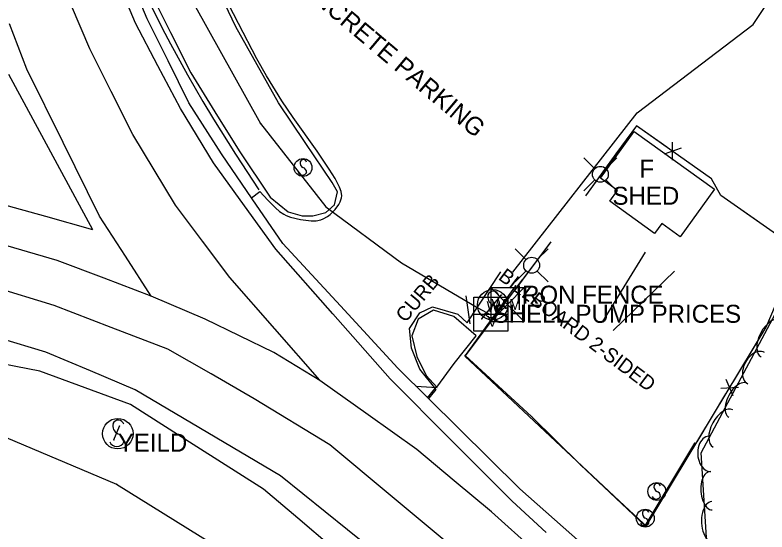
# Model space of a CAD drawing. Extents: x 1441650 to 1491889, y 345904 to 358319.
# Drawn here: x 1442426.6 to 1442635.7, y 357190.8 to 357334.5 of the extents above; entities that cross this region are included whole.
import ezdxf

# ---------------------------------------------------------------- set-up
doc = ezdxf.new("R2010")
doc.units = 0
for name, color, linetype in [('S_BUILDING', 7, 'Continuous'), ('S_BUILDING_ANNOT', 7, 'Continuous'), ('S_CURB', 7, 'Continuous'), ('S_CURB_ANNOT', 7, 'Continuous'), ('S_EDGE_CONCRETE', 7, 'Continuous'), ('S_EDGE_PAVEMENT', 7, 'Continuous'), ('S_FENCE', 7, 'Continuous'), ('S_FENCE_ANNOT', 7, 'Continuous'), ('S_MSC_PT_SYM', 7, 'Continuous'), ('S_PARKING', 7, 'Continuous'), ('S_PARKING_ANNOT', 7, 'Continuous'), ('S_PAVEMENT_CROWN', 7, 'Continuous'), ('S_SHOULDER', 7, 'Continuous'), ('S_SIGN', 7, 'Continuous'), ('S_SIGN_ANNOT', 7, 'Continuous'), ('S_TREE', 7, 'Continuous'), ('S_UTILITY_POLE', 7, 'Continuous'), ('S_UTL_PT_SYM', 7, 'Continuous'), ('S_WATER_UTILITIES', 7, 'Continuous')]:
    doc.layers.add(name, color=color, linetype=linetype)

msp = doc.modelspace()

# ---------------------------------------------------------------- linework, layer by layer
at = {"layer": 'S_BUILDING'}
msp.add_lwpolyline([(1442598.85, 357302.17), (1442621.13, 357286.07), (1442611.57, 357272.84), (1442606.46, 357276.53), (1442604.47, 357273.79), (1442592.06, 357282.76), (1442594.21, 357285.73), (1442589.45, 357289.17)], close=True, dxfattribs=at)
at = {"layer": 'S_CURB'}
msp.add_lwpolyline([(1442464.25, 357340.83), (1442469.85, 357329.65), (1442475.45, 357318.47), (1442482.16, 357307.59), (1442488.88, 357296.71), (1442497.57, 357283.85), (1442502.55, 357279.77), (1442506.49, 357278.64), (1442509.44, 357278.67), (1442513.02, 357279.61), (1442515.42, 357281.72), (1442516.3, 357285.33), (1442514.78, 357287.98), (1442507.32, 357299.06), (1442499.86, 357310.13), (1442487.99, 357331.18), (1442478.69, 357350.71)], dxfattribs=at)
msp.add_lwpolyline([(1442554.87, 357245.36), (1442548.6, 357250.71), (1442542.98, 357252.42), (1442538.71, 357249.97), (1442536.97, 357245.34), (1442538.32, 357239.58), (1442540.96, 357234.33), (1442543.88, 357231.01), (1442548.78, 357237.63)], close=True, dxfattribs=at)
at = {"layer": 'S_CURB_ANNOT'}
for p, q in [((1442553.16, 357248.64), (1442552.04, 357256.4)), ((1442544.01, 357230.87), (1442538.09, 357231.25))]:
    msp.add_line(p, q, dxfattribs=at)
at = {"layer": 'S_EDGE_CONCRETE'}
for points in [[(1442492.39, 357283.72), (1442494.68, 357285.41), (1442496.92, 357283.03), (1442499.07, 357280.86), (1442500.19, 357279.92), (1442501.37, 357279.14), (1442501.99, 357278.81), (1442503.25, 357278.31), (1442506.01, 357277.67), (1442508.91, 357277.31), (1442510.33, 357277.33), (1442511.68, 357277.58), (1442512.32, 357277.8), (1442513.53, 357278.47), (1442514.28, 357279.06), (1442515.64, 357280.48), (1442516.66, 357281.84), (1442517.05, 357282.56), (1442517.41, 357283.67), (1442517.46, 357284.25), (1442517.3, 357285.44), (1442516.88, 357286.64), (1442515.59, 357289.02), (1442513.94, 357291.68), (1442510.6, 357296.68), (1442503.98, 357306.01), (1442500.8, 357310.69), (1442496.57, 357317.59), (1442493.87, 357322.37), (1442488.7, 357332.13), (1442484.43, 357340.5)], [(1442541.81, 357227.99), (1442543.72, 357230.38), (1442539.14, 357236.06), (1442536.88, 357241.86), (1442536.34, 357247.38), (1442539.18, 357251.71), (1442542.69, 357253.36), (1442549.75, 357251.31), (1442552.37, 357248.97), (1442561.72, 357263.08)]]:
    msp.add_lwpolyline(points, dxfattribs=at)
at = {"layer": 'S_EDGE_PAVEMENT'}
for points in [[(1442574.34, 357190.65), (1442564.91, 357199.31), (1442547.91, 357216.35), (1442530.91, 357233.4), (1442515.01, 357251.41), (1442499.11, 357269.42), (1442490.43, 357281.42), (1442481.75, 357293.41), (1442472.58, 357308.49), (1442466.31, 357320.36), (1442460.05, 357332.22), (1442454.85, 357344.64), (1442449.65, 357357.05), (1442445.57, 357369.87), (1442441.49, 357382.69), (1442438.33, 357395.97), (1442435.18, 357409.25), (1442432.26, 357424.91), (1442430.21, 357443.25)], [(1442441.56, 357408.09), (1442443.15, 357400.69), (1442444.3, 357395.77), (1442446.77, 357386), (1442449.67, 357375.7), (1442451.24, 357370.58), (1442453.77, 357362.97), (1442455.66, 357357.78), (1442456.98, 357354.35), (1442459.77, 357347.53), (1442464.3, 357337.45), (1442467.54, 357330.83), (1442469.8, 357326.46), (1442474.51, 357317.84), (1442478.84, 357310.42), (1442481.81, 357305.52), (1442487.92, 357295.83), (1442494.36, 357285.94)], [(1442464.47, 357256.33), (1442457.26, 357267.43), (1442450.05, 357278.54), (1442439.95, 357299.02), (1442429.85, 357319.49), (1442425, 357332.04)], [(1442464.45, 357256.37), (1442451.39, 357261.32), (1442438.33, 357266.27), (1442416.31, 357272.65), (1442394.3, 357279.03)], [(1442537.77, 357176.4), (1442519.07, 357191.42), (1442500.38, 357206.43), (1442480.21, 357218.38), (1442460.04, 357230.33), (1442447.59, 357235.57), (1442435.15, 357240.82), (1442422.16, 357244.67)]]:
    msp.add_lwpolyline(points, dxfattribs=at)
at = {"layer": 'S_FENCE'}
for p, q in [((1442609.48, 357294.12), (1442609.49, 357299.12)), ((1442611.84, 357297.47), (1442607.14, 357295.78)), ((1442565.77, 357259.26), (1442551.76, 357239.88)), ((1442551.76, 357239.88), (1442570.29, 357222.93)), ((1442626.38, 357228.62), (1442624.36, 357233.2)), ((1442622.88, 357230.74), (1442627.86, 357231.08)), ((1442570.29, 357222.93), (1442583.87, 357209.47)), ((1442601.89, 357192.54), (1442615.64, 357215.51)), ((1442583.87, 357209.47), (1442601.89, 357192.54))]:
    msp.add_line(p, q, dxfattribs=at)
for points in [[(1442575.65, 357271.44), (1442551.66, 357239.62), (1442602.13, 357192.41), (1442635.49, 357247.69), (1442644.62, 357269.18), (1442622.96, 357284.3), (1442620.33, 357288.98), (1442599.42, 357303.72), (1442585.31, 357284.25)], [(1442607.85, 357297.78), (1442599.42, 357303.72), (1442593.74, 357295.88)], [(1442593.74, 357295.88), (1442585.31, 357284.25)], [(1442625.72, 357282.37), (1442622.96, 357284.3), (1442620.33, 357288.98), (1442611.12, 357295.47)], [(1442642.12, 357270.93), (1442625.72, 357282.37)], [(1442575.65, 357271.44), (1442567.06, 357260.05)], [(1442626.4, 357232.62), (1442635.49, 357247.69), (1442636.43, 357249.89)], [(1442616.31, 357215.89), (1442624.34, 357229.2)], [(1442586.79, 357206.76), (1442601.39, 357193.1)]]:
    msp.add_lwpolyline(points, dxfattribs=at)
at = {"layer": 'S_MSC_PT_SYM'}
for points in [[(1442565.77, 357259.26), (1442565.77, 357259.31), (1442565.77, 357259.26), (1442565.72, 357259.26), (1442565.77, 357259.26), (1442565.77, 357259.21), (1442565.77, 357259.26), (1442565.82, 357259.26)], [(1442561.91, 357256.7), (1442561.91, 357256.75), (1442561.91, 357256.7), (1442561.86, 357256.7), (1442561.91, 357256.7), (1442561.91, 357256.65), (1442561.91, 357256.7), (1442561.96, 357256.7)], [(1442556.42, 357250.04), (1442556.42, 357250.09), (1442556.42, 357250.04), (1442556.37, 357250.04), (1442556.42, 357250.04), (1442556.42, 357249.99), (1442556.42, 357250.04), (1442556.47, 357250.04)], [(1442551.76, 357239.88), (1442551.76, 357239.93), (1442551.76, 357239.88), (1442551.71, 357239.88), (1442551.76, 357239.88), (1442551.76, 357239.83), (1442551.76, 357239.88), (1442551.81, 357239.88)], [(1442570.29, 357222.93), (1442570.29, 357222.98), (1442570.29, 357222.93), (1442570.24, 357222.93), (1442570.29, 357222.93), (1442570.29, 357222.88), (1442570.29, 357222.93), (1442570.34, 357222.93)], [(1442455.61, 357220.25), (1442455.61, 357220.3), (1442455.61, 357220.25), (1442455.56, 357220.25), (1442455.61, 357220.25), (1442455.61, 357220.2), (1442455.61, 357220.25), (1442455.66, 357220.25)], [(1442454.09, 357216.37), (1442454.09, 357216.42), (1442454.09, 357216.37), (1442454.04, 357216.37), (1442454.09, 357216.37), (1442454.09, 357216.32), (1442454.09, 357216.37), (1442454.14, 357216.37)], [(1442615.64, 357215.51), (1442615.64, 357215.56), (1442615.64, 357215.51), (1442615.59, 357215.51), (1442615.64, 357215.51), (1442615.64, 357215.46), (1442615.64, 357215.51), (1442615.69, 357215.51)], [(1442583.87, 357209.47), (1442583.87, 357209.52), (1442583.87, 357209.47), (1442583.82, 357209.47), (1442583.87, 357209.47), (1442583.87, 357209.42), (1442583.87, 357209.47), (1442583.92, 357209.47)], [(1442601.89, 357192.54), (1442601.89, 357192.59), (1442601.89, 357192.54), (1442601.84, 357192.54), (1442601.89, 357192.54), (1442601.89, 357192.49), (1442601.89, 357192.54), (1442601.94, 357192.54)]]:
    msp.add_lwpolyline(points, dxfattribs=at)
at = {"layer": 'S_PARKING'}
for points in [[(1442565.04, 357263.02), (1442599.67, 357307.29), (1442631.89, 357331.9), (1442642.01, 357347.19), (1442644.13, 357358.03), (1442611.93, 357355.44)], [(1442541.28, 357228.05), (1442543.72, 357231.02)]]:
    msp.add_lwpolyline(points, dxfattribs=at)
at = {"layer": 'S_PAVEMENT_CROWN'}
for points in [[(1442511.33, 357232.96), (1442498.81, 357247.25), (1442486.3, 357261.54), (1442478.75, 357271.62), (1442471.19, 357281.69), (1442459.34, 357301.32), (1442453.35, 357313.23), (1442447.36, 357325.14), (1442442.26, 357337.09), (1442437.16, 357349.05), (1442433.21, 357362.12), (1442429.26, 357375.19), (1442425.16, 357390.43)], [(1442547.65, 357187.12), (1442530.91, 357201.04), (1442514.17, 357214.97), (1442493.14, 357227.82), (1442481.12, 357234.72), (1442469.09, 357241.63), (1442453.29, 357247.68), (1442437.48, 357253.74), (1442420.36, 357258.98)], [(1442743.84, 357033.72), (1442725.96, 357049.57), (1442708.08, 357065.42), (1442697.34, 357075.2), (1442686.61, 357084.97), (1442675.88, 357094.74), (1442665.15, 357104.52), (1442654.91, 357113.15), (1442644.67, 357121.79), (1442634.43, 357130.42), (1442624.19, 357139.06), (1442613.92, 357148.01), (1442603.65, 357156.95), (1442593.38, 357165.9), (1442583.11, 357174.85), (1442571.1, 357185.6), (1442559.09, 357196.36), (1442548.72, 357205.05), (1442538.36, 357213.74), (1442524.84, 357223.32), (1442511.32, 357232.91), (1442498.55, 357240.65), (1442479.49, 357249.92), (1442464.46, 357256.35)]]:
    msp.add_lwpolyline(points, dxfattribs=at)
at = {"layer": 'S_SHOULDER'}
for points in [[(1442586.33, 357185.74), (1442576.68, 357194.26), (1442567.03, 357202.79), (1442550.06, 357219.57), (1442533.09, 357236.35), (1442517.08, 357253.68), (1442501.06, 357271.01), (1442492.55, 357283.44), (1442484.04, 357295.88), (1442474.91, 357310.13), (1442469.13, 357321.77), (1442463.35, 357333.4), (1442458.13, 357345.9), (1442452.91, 357358.39), (1442449.09, 357371.04), (1442445.26, 357383.68), (1442441.69, 357396.99), (1442438.11, 357410.31), (1442435.68, 357425.48), (1442433.48, 357443.75)], [(1442448.22, 357274.79), (1442436.53, 357296.4), (1442424.83, 357318.01)], [(1442448.22, 357274.79), (1442435.12, 357278.45), (1442422.01, 357282.1), (1442408.91, 357285.76), (1442395.8, 357289.42)], [(1442514.83, 357186.49), (1442505.28, 357194.59), (1442495.72, 357202.7), (1442477.19, 357214.44), (1442458.65, 357226.19), (1442446.07, 357230.85), (1442433.49, 357235.5), (1442419.57, 357238.15)]]:
    msp.add_lwpolyline(points, dxfattribs=at)
at = {"layer": 'S_SIGN'}
for p, q in [((1442590.05, 357249.33), (1442601.94, 357268.54)), ((1442610.02, 357263.32), (1442593.01, 357246.83)), ((1442556.42, 357250.04), (1442561.91, 357256.7)), ((1442454.09, 357216.37), (1442455.61, 357220.25))]:
    msp.add_line(p, q, dxfattribs=at)
for centre, radius in [((1442506.69, 357292.1), 2.49), ((1442559.45, 357253.94), 4.24), ((1442455.16, 357218.11), 4.24), ((1442605.12, 357202.05), 2.49), ((1442601.9, 357194.62), 2.49)]:
    msp.add_circle(centre, radius, dxfattribs=at)
for centre, radius, start, end in [((1442507.38, 357293.42), 1.5, 167.1196, 241.9813), ((1442506.76, 357293.36), 0.95, 16.5258, 156.8957), ((1442506.54, 357291.27), 1.28, 204.641, 335.359), ((1442506.28, 357290.75), 1.4, 358.6529, 73.7063), ((1442559.57, 357256.09), 1.62, 16.5258, 156.8957), ((1442560.61, 357256.19), 2.55, 167.1196, 241.9813), ((1442558.75, 357251.66), 2.38, 358.6529, 73.7063), ((1442559.19, 357252.54), 2.17, 204.641, 335.359), ((1442455.29, 357220.26), 1.62, 16.5258, 156.8957), ((1442456.33, 357220.36), 2.55, 167.1196, 241.9813), ((1442454.46, 357215.83), 2.38, 358.6529, 73.7063), ((1442454.9, 357216.71), 2.17, 204.641, 335.359), ((1442605.8, 357203.38), 1.5, 167.1196, 241.9813), ((1442605.19, 357203.32), 0.95, 16.5258, 156.8957), ((1442604.96, 357201.23), 1.28, 204.641, 335.359), ((1442604.7, 357200.71), 1.4, 358.6529, 73.7063), ((1442601.98, 357195.89), 0.95, 16.5258, 156.8957), ((1442602.59, 357195.95), 1.5, 167.1196, 241.9813), ((1442601.49, 357193.28), 1.4, 358.6529, 73.7063), ((1442601.75, 357193.8), 1.28, 204.641, 335.359)]:
    msp.add_arc(centre, radius, start, end, dxfattribs=at)
at = {"layer": 'S_TREE'}
msp.add_lwpolyline([(1442777.03, 357120.01), (1442741.65, 357139.97), (1442709.3, 357167.21), (1442677.75, 357179.14), (1442639.11, 357179.13), (1442619.07, 357186.32), (1442617.48, 357212.76), (1442643.33, 357261.28), (1442650.49, 357276.8), (1442655.34, 357292.79), (1442659.99, 357316.87), (1442676.42, 357350.41), (1442691.66, 357380.54), (1442706.42, 357414.34), (1442711.66, 357444.66)], dxfattribs=at)
for centre, major_axis, ratio, start_param, end_param in [((1442636.86, 357244.63), (-2.75, -5.18), 0.549799, 3.139643, 6.281235), ((1442632.74, 357236.35), (-2.32, -4.37), 0.684959, 3.138399, 6.279992), ((1442627.67, 357227.39), (-2.51, -4.72), 0.540424, 3.139703, 6.281296), ((1442623.51, 357219.57), (-2.75, -5.18), 0.549799, 3.139643, 6.281235), ((1442619.88, 357212.52), (0.27, -4.93), 0.686618, 3.14847, 6.290063), ((1442620.23, 357202.26), (0.31, -5.32), 0.541738, 3.145652, 6.287245), ((1442620.76, 357193.44), (0.34, -5.84), 0.551136, 3.145783, 6.287376)]:
    msp.add_ellipse(centre, major_axis=major_axis, ratio=ratio, start_param=start_param, end_param=end_param, dxfattribs=at)
at = {"layer": 'S_UTILITY_POLE'}
for p, q in [((1442587.8, 357291.8), (1442584.82, 357294.79)), ((1442590.98, 357291.8), (1442593.96, 357294.79)), ((1442587.8, 357288.63), (1442584.82, 357285.64)), ((1442590.98, 357288.63), (1442593.96, 357285.64)), ((1442568.68, 357266.52), (1442565.7, 357269.51)), ((1442571.86, 357266.52), (1442574.85, 357269.51)), ((1442568.68, 357263.34), (1442565.7, 357260.36)), ((1442571.86, 357263.34), (1442574.85, 357260.36))]:
    msp.add_line(p, q, dxfattribs=at)
for centre in [(1442589.4, 357290.22), (1442570.28, 357264.94)]:
    msp.add_circle(centre, 2.21, dxfattribs=at)
at = {"layer": 'S_UTL_PT_SYM'}
for points in [[(1442494.82, 357304.33), (1442494.82, 357304.38), (1442494.82, 357304.33), (1442494.77, 357304.33), (1442494.82, 357304.33), (1442494.82, 357304.28), (1442494.82, 357304.33), (1442494.87, 357304.33)], [(1442513.07, 357281.19), (1442513.07, 357281.24), (1442513.07, 357281.19), (1442513.02, 357281.19), (1442513.07, 357281.19), (1442513.07, 357281.14), (1442513.07, 357281.19), (1442513.12, 357281.19)], [(1442534.1, 357265.57), (1442534.1, 357265.62), (1442534.1, 357265.57), (1442534.05, 357265.57), (1442534.1, 357265.57), (1442534.1, 357265.52), (1442534.1, 357265.57), (1442534.15, 357265.57)], [(1442555.32, 357253.06), (1442555.32, 357253.11), (1442555.32, 357253.06), (1442555.27, 357253.06), (1442555.32, 357253.06), (1442555.32, 357253.01), (1442555.32, 357253.06), (1442555.37, 357253.06)], [(1442558.92, 357251.16), (1442558.92, 357251.21), (1442558.92, 357251.16), (1442558.87, 357251.16), (1442558.92, 357251.16), (1442558.92, 357251.11), (1442558.92, 357251.16), (1442558.97, 357251.16)], [(1442454.77, 357204.1), (1442454.77, 357204.15), (1442454.77, 357204.1), (1442454.72, 357204.1), (1442454.77, 357204.1), (1442454.77, 357204.05), (1442454.77, 357204.1), (1442454.82, 357204.1)]]:
    msp.add_lwpolyline(points, dxfattribs=at)
at = {"layer": 'S_WATER_UTILITIES'}
for p, q in [((1442476.3, 357337.64), (1442494.82, 357304.33)), ((1442494.82, 357304.33), (1442513.07, 357281.19)), ((1442513.07, 357281.19), (1442534.1, 357265.57)), ((1442534.1, 357265.57), (1442555.32, 357253.06)), ((1442558.91, 357258.75), (1442568.25, 357258.75)), ((1442558.91, 357258.75), (1442558.91, 357249.26)), ((1442558.91, 357258.75), (1442568.25, 357249.26)), ((1442568.25, 357258.75), (1442558.91, 357249.26)), ((1442568.25, 357258.75), (1442568.25, 357249.26)), ((1442554.21, 357256.07), (1442563.63, 357256.07)), ((1442554.21, 357246.65), (1442554.21, 357256.07)), ((1442563.63, 357256.07), (1442563.63, 357246.65)), ((1442555.32, 357253.06), (1442558.92, 357251.16)), ((1442554.21, 357251.38), (1442563.63, 357251.38)), ((1442558.91, 357249.26), (1442568.25, 357249.26)), ((1442563.63, 357246.65), (1442554.21, 357246.65)), ((1442410.42, 357222.81), (1442454.77, 357204.1)), ((1442454.77, 357204.1), (1442498.11, 357177.29))]:
    msp.add_line(p, q, dxfattribs=at)

# ---------------------------------------------------------------- texts
at = {"layer": 'S_BUILDING_ANNOT'}
for s, p in [('F', (1442600.27, 357289.26)), ('SHED', (1442592.77, 357281.76))]:
    msp.add_text(s, height=5, dxfattribs=at).set_placement(p)
at = {"layer": 'S_CURB_ANNOT'}
msp.add_text('CURB', height=4, rotation=49.8977, dxfattribs=at).set_placement((1442535.17, 357248.78))
at = {"layer": 'S_FENCE_ANNOT'}
msp.add_text('IRON FENCE', height=5, dxfattribs=at).set_placement((1442565.77, 357254.26))
at = {"layer": 'S_PARKING_ANNOT'}
msp.add_text('CONCRETE PARKING', height=5.0003, rotation=319.8977, dxfattribs=at).set_placement((1442501.56, 357344.92))
at = {"layer": 'S_SIGN_ANNOT'}
msp.add_text('BILLBOARD 2-SIDED', height=4.0002, rotation=323.1008, dxfattribs=at).set_placement((1442560.76, 357261.19))
for s, p in [('SHELL PUMP PRICES', (1442559.45, 357248.94)), ('YEILD', (1442455.16, 357213.11))]:
    msp.add_text(s, height=5, dxfattribs=at).set_placement(p)
at = {"layer": 'S_WATER_UTILITIES'}
for s, p in [('W M', (1442559.11, 357252.52)), ('W', (1442557.76, 357251.91)), ('V', (1442558, 357247.85))]:
    msp.add_text(s, height=3, rotation=360, dxfattribs=at).set_placement(p)

doc.saveas('drawing.dxf')
